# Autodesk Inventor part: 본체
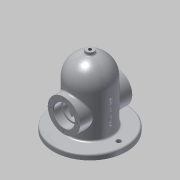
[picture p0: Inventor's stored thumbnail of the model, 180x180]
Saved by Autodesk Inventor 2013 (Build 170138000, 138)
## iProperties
Created: 2019-11
Part Number: 본체
Material: 알루미늄 6061
Document SubType Name: Modeling
Designer: Administrator
Density: 2.71 g/cm^3
Mass: 1186.55 g
Surface Area: 921.221 cm^2
Volume: 437.841 cm^3
Author: Administrator
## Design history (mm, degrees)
sketch "스케치1"
  geometry: C1 r 40 at (0, 0); 1 further point
  constraints: 1 centre point, 1 coincident
  dimensions: "d0" = 80 diameter of C1
extrude "돌출1" new body sketch "스케치1" distance "d2" = 90; taper "d3" = 0 deg
sketch "스케치2"
  geometry: L1 (40, 90)-(-40, 90) reference; L2 (0, 90)-(0, 130); L3 (-40, 90)-(0, 90); A1 r 40 centre (0, 90) between (0, 130) and (-40, 90); 1 further point
  constraints: 4 end point, 2 point on circle, 1 centre point, 1 coincident, 1 collinear, 1 midpoint, 1 perpendicular
revolve "회전1" sketch "스케치2" stored, may be unused: angle "d10" = 90 deg
sketch "스케치3"
  geometry: C1 r 40 at (0, 0) reference; C2 r 30 at (0, 0)
  constraints: 1 centre point, 1 coincident
  dimensions: "d11" = 60 diameter of C2
extrude "돌출2" cut sketch "스케치3" distance "d13" = 90; taper "d14" = 0 deg
sketch "스케치4"
  geometry: L1 (40, 90)-(40, 0) reference; L2 (40, 0)-(30, 0) reference; L3 (30, 0)-(30, 90) reference; L4 (30, 90)-(-30, 90) reference; L5 (-30, 90)-(-30, 0) reference; L6 (-30, 0)-(-40, 0) reference; L7 (-40, 0)-(-40, 90) reference; L8 (30, 90)-(-30, 90) reference; L9 (0, 90)-(0, 120); L10 (-30, 90)-(0, 90); A1 r 40 centre (0, 90) between (40, 90) and (0, 130) reference; A2 r 40 centre (0, 90) between (0, 130) and (-40, 90) reference; A3 r 30 centre (0, 90) between (0, 120) and (-30, 90); 1 further point
  constraints: 4 end point, 2 point on circle, 1 centre point, 1 coincident, 1 collinear, 1 perpendicular
revolve "회전2" sketch "스케치4" stored, may be unused: angle "d15" = 90 deg
sketch "스케치5"
  geometry: C1 r 70 at (0, 0); 1 further point
  constraints: 1 centre point, 1 coincident
  dimensions: "d16" = 140 diameter of C1
extrude "돌출3" join sketch "스케치5" distance "d18" = 10; taper "d19" = 0 deg
sketch "스케치6"
  geometry: C1 r 70 at (0, 0) reference; C2 r 70 at (0, 0) reference; C3 r 4.5 at (55, 0); C4 r 4.5 at (-55, 0); A1 r 55 centre (0, 0) between (55, 0) and (-55, 0)
  constraints: 3 centre point, 2 horizontal alignment, 2 point on circle, 1 coincident, 1 equal radius
  dimensions: "d20" = 110 diameter of A1; "d22" = 9 diameter of C3
extrude "돌출4" cut sketch "스케치6" stored distance "d23" = 10; taper "d24" = 0 deg
node "작업 평면1"
sketch "스케치7"
  geometry: C1 r 31 at (0, 50); 1 further point
  constraints: 1 centre point, 1 vertical alignment
  dimensions: "d26" = 62 diameter of C1; "d28" = 50 distance of C1.centre point (0, 0)
extrude "돌출5" join sketch "스케치7" stored distance "d29" = 10; taper "d30" = 0 deg
node "작업 평면2"
sketch "스케치8"
  geometry: C1 r 31 at (0, 50); 1 further point
  constraints: 1 centre point, 1 vertical alignment
  dimensions: "d32" = 62 diameter of C1; "d34" = 50 distance of C1.centre point (0, 0)
extrude "돌출6" join sketch "스케치8" stored distance "d35" = 10; taper "d36" = 0 deg
sketch "스케치9"
  geometry: C1 r 31 at (0, 0) reference; C2 r 20 at (0, 0); 1 further point
  constraints: 1 centre point, 1 coincident
  dimensions: "d37" = 40 diameter of C2
extrude "돌출7" cut sketch "스케치9" distance "d39" = 15; taper "d40" = 0 deg
fillet "모깎기1" dims "d41" = 0.3
sketch "스케치10"
  geometry: C1 r 19.7 at (0, 0) reference; C2 r 16.5 at (0, 0); 1 further point
  constraints: 1 centre point, 1 coincident
  dimensions: "d42" = 33 diameter of C2
extrude "돌출8" cut sketch "스케치10" stored distance "d44" = 15; taper "d45" = 0 deg
sketch "스케치11"
  geometry: C1 r 31 at (0, 0) reference; C2 r 20 at (0, 0); 1 further point
  constraints: 1 centre point, 1 coincident
  dimensions: "d46" = 40 diameter of C2
extrude "돌출9" cut sketch "스케치11" distance "d48" = 15; taper "d49" = 0 deg
fillet "모깎기2" dims "d50" = 0.3
sketch "스케치12"
  geometry: C1 r 19.7 at (0, 0) reference; C2 r 16.5 at (0, 0); 1 further point
  constraints: 1 centre point, 1 coincident
  dimensions: "d51" = 33 diameter of C2
extrude "돌출10" cut sketch "스케치12" stored distance "d53" = 15; taper "d54" = 0 deg
sketch "스케치13" dims "d55" = 52
  geometry: C1 r 20 at (0, 0) reference; C2 r 31 at (0, 0) reference; 6 further points
  constraints: 2 vertical alignment, 1 coincident, 7 other
  dimensions: "d59" = 360 deg dimension on C1.centre point (0, 26) (derived)
hole "구멍1" sketch "스케치13" at (0, 26), (-26, 0), (0, -26), (26, 0) diameter "d61" = 3.242; stored, may be unused: countersink angle "d65" = 90 deg, drill point angle "d67" = 118 deg; dims "d62" = 8, "d63" = 4, "d64" = 2, "d66" = 10
sketch "스케치14" dims "d68" = 52
  geometry: C1 r 20 at (0, 0) reference; C2 r 31 at (0, 0) reference; 6 further points
  constraints: 2 vertical alignment, 1 coincident, 7 other
  dimensions: "d72" = 360 deg dimension on C1.centre point (0, 26) (derived)
hole "구멍2" sketch "스케치14" at (0, 26), (-26, 0), (0, -26), (26, 0) diameter "d74" = 3.242; stored, may be unused: countersink angle "d78" = 90 deg, drill point angle "d80" = 118 deg; dims "d75" = 8, "d76" = 4, "d77" = 2, "d79" = 10
node "작업 평면3"
sketch "스케치15"
  geometry: C1 r 7.5 at (0, 0); 1 further point
  constraints: 1 centre point, 1 coincident
  dimensions: "d82" = 15 diameter of C1
extrude "돌출11" join sketch "스케치15" stored distance "d84" = 15; taper "d85" = 0 deg
sketch "스케치16"
  geometry: C1 r 7.5 at (0, 0) reference; C2 r 3 at (0, 0)
  constraints: 1 centre point, 1 coincident
  dimensions: "d86" = 6 diameter of C2
extrude "돌출12" cut sketch "스케치16" stored distance "d88" = 15; taper "d89" = 0 deg
feature "스레드1" dims "d90" = 10, "d91" = 0
node "작업 평면4"
sketch "스케치17"
  geometry: L1 (-70, 0)-(70, 0) reference; 4 further points
  constraints: 1 coincident, 1 midpoint, 1 vertical alignment, 1 other
  dimensions: "d92" = 50 distance from line of point (0, 50) L1
feature "엠보싱1" sketch "스케치17" dims "d2" = 90, "d93" = 0.5, "d94" = 0
fillet "모깎기3" dims "d95" = 3
chamfer "모따기1" distance "d96" = 1; stored, may be unused: second distance "d97" = 2, angle "d98" = 45 deg
chamfer "모따기2" distance "d99" = 1; stored, may be unused: second distance "d100" = 2, angle "d101" = 45 deg
node "솔리드1"
node "절단 모서리 투영1"
other parameters: "d81" = 135
